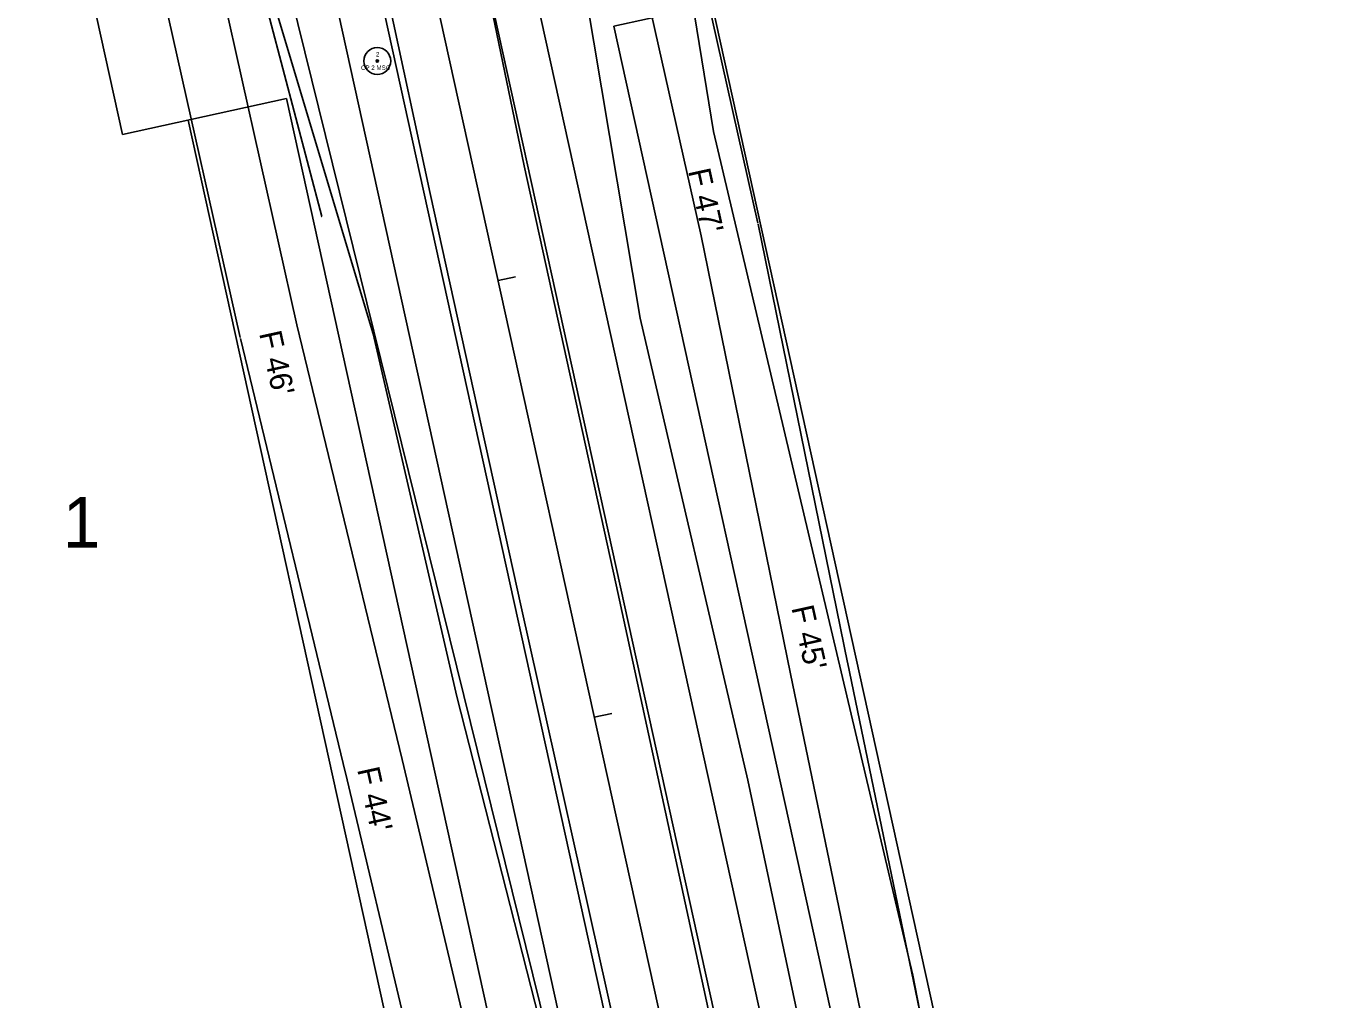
# Model space of a CAD drawing. Extents: x 2519952 to 2531965, y 848341 to 887632.
# Drawn here: x 2524206.7 to 2524500.7, y 856689.7 to 856907.4 of the extents above; entities that cross this region are included whole.
import ezdxf

# ---------------------------------------------------------------- set-up
doc = ezdxf.new("R2010")
doc.units = 0
for name, color, linetype in [('RD_EV_JW', 7, 'Continuous'), ('RD_EX_DV_Prop', 7, 'Continuous'), ('RD_EX_DV_TX_Prop', 7, 'Continuous'), ('RD_EX_H2O', 7, 'Continuous'), ('RD_EX_Road', 7, 'Continuous'), ('RD_EX_RW', 7, 'Continuous'), ('RD_EX_VEG', 7, 'Continuous'), ('RD_HC_Cl', 7, 'Continuous'), ('RD_HC_Data', 7, 'Continuous'), ('RD_HC_Data_Tic', 7, 'Continuous'), ('RD_HC_txCode', 7, 'Continuous'), ('RD_PD_CstnLmt', 7, 'Continuous'), ('RD_PD_DR_ErosCtrl', 7, 'Continuous'), ('RD_PD_Final_TrvlWay', 7, 'Continuous'), ('RD_PD_GR', 7, 'Continuous'), ('RD_PD_RW', 7, 'Continuous'), ('RD_PD_TX_CstnLmt', 7, 'Continuous'), ('RD_SMD_Locator', 7, 'Continuous')]:
    doc.layers.add(name, color=color, linetype=linetype)

msp = doc.modelspace()

# ---------------------------------------------------------------- linework, layer by layer
at = {"layer": 'RD_EV_JW'}
for points in [[(2524424.95, 856473.85), (2524390.5, 856633.35), (2524368.09, 856738.8), (2524344.01, 856842.14), (2524328.51, 856934.61), (2524317.15, 857018.9), (2524297.91, 857028.24)], [(2524307.83, 856393.41), (2524347.51, 856441.44), (2524366.03, 856458.61), (2524362.85, 856506.49), (2524327.82, 856660.19), (2524303.01, 856757.56), (2524284.34, 856838.66), (2524260.99, 856916.53), (2524250.82, 856955.25), (2524240.58, 856992.67)]]:
    msp.add_lwpolyline(points, dxfattribs=at)
at = {"layer": 'RD_EX_DV_Prop'}
for p, q in [((2524163.74, 857176.23), (2524228.26, 856883.25)), ((2524338.13, 856907.45), (2524445.65, 856419.14)), ((2524228.26, 856883.25), (2524264.88, 856891.32)), ((2524264.88, 856891.32), (2524372.41, 856403.02)), ((2524264.88, 856891.32), (2524372.41, 856403.02))]:
    msp.add_line(p, q, dxfattribs=at)
at = {"layer": 'RD_EX_H2O'}
msp.add_lwpolyline([(2524272.81, 856864.89), (2524243.76, 856975.33), (2524236.35, 856986.49), (2524250.55, 857018.32), (2524297.65, 857029.48), (2524307.91, 857029.77)], dxfattribs=at)
at = {"layer": 'RD_EX_Road'}
for p, q in [((2524318.05, 856876.23), (2524297.66, 856974.69)), ((2524297.08, 856870.07), (2524275.55, 856969.68)), ((2524338.64, 856782.48), (2524318.05, 856876.23)), ((2524317.42, 856777.55), (2524297.08, 856870.07)), ((2524359.59, 856685.95), (2524338.64, 856782.48)), ((2524339.18, 856679.93), (2524317.42, 856777.55))]:
    msp.add_line(p, q, dxfattribs=at)
at = {"layer": 'RD_EX_RW'}
for p, q in [((2524163.74, 857176.23), (2524228.26, 856883.25)), ((2524338.13, 856907.44), (2524374.75, 856915.51)), ((2524338.13, 856907.44), (2524445.65, 856419.14)), ((2524228.26, 856883.25), (2524264.88, 856891.32)), ((2524264.88, 856891.32), (2524372.41, 856403.02))]:
    msp.add_line(p, q, dxfattribs=at)
at = {"layer": 'RD_EX_VEG'}
for points in [[(2524280.31, 856341.99), (2524372.33, 856422.74), (2524324.66, 856676.58), (2524252.03, 856970.65), (2524249.14, 857000.39)], [(2524478.83, 856499.73), (2524446.25, 856482.83), (2524405.01, 856695.22), (2524360.42, 856883.93), (2524342.44, 856994.33)]]:
    msp.add_lwpolyline(points, dxfattribs=at)
at = {"layer": 'RD_HC_Cl'}
msp.add_line((2524121.25, 857717.97), (2524677.84, 855190.33), dxfattribs=at)
at = {"layer": 'RD_HC_Data'}
for radius in [3, 0.282]:
    msp.add_circle((2524285.22, 856899.68), radius, dxfattribs=at)
at = {"layer": 'RD_HC_Data_Tic'}
for p, q in [((2524312.26, 856850.55), (2524316.16, 856851.41)), ((2524333.76, 856752.89), (2524337.67, 856753.75))]:
    msp.add_line(p, q, dxfattribs=at)
at = {"layer": 'RD_PD_CstnLmt'}
for p, q in [((2524335.83, 856958.14), (2524357.69, 856860.55)), ((2524245.41, 856938.23), (2524267.26, 856840.64)), ((2524357.69, 856860.55), (2524377.69, 856762.56)), ((2524267.26, 856840.64), (2524290.79, 856743.43)), ((2524377.69, 856762.56), (2524397.95, 856664.63)), ((2524290.79, 856743.43), (2524313.87, 856646.11))]:
    msp.add_line(p, q, dxfattribs=at)
at = {"layer": 'RD_PD_DR_ErosCtrl'}
for p, q in [((2524348.52, 856960.98), (2524370.37, 856863.39)), ((2524232.72, 856935.39), (2524254.57, 856837.8)), ((2524370.43, 856863.15), (2524390.43, 856765.16)), ((2524254.62, 856837.58), (2524278.15, 856740.37)), ((2524390.42, 856765.2), (2524410.68, 856667.26)), ((2524278.14, 856740.43), (2524301.22, 856643.11))]:
    msp.add_line(p, q, dxfattribs=at)
at = {"layer": 'RD_PD_Final_TrvlWay'}
for p, q in [((2524221.83, 857317.02), (2524496.02, 856071.85)), ((2524198.39, 857311.86), (2524472.58, 856066.69))]:
    msp.add_line(p, q, dxfattribs=at)
at = {"layer": 'RD_PD_GR'}
for p, q in [((2524311.97, 856954.16), (2524470.57, 856233.92)), ((2524376.52, 856456.4), (2524269, 856944.7))]:
    msp.add_line(p, q, dxfattribs=at)
at = {"layer": 'RD_PD_RW'}
for p, q in [((2524360.1, 856912.28), (2524467.63, 856423.98)), ((2524242.91, 856886.48), (2524377.31, 856276.1))]:
    msp.add_line(p, q, dxfattribs=at)
at = {"layer": 'RD_SMD_Locator'}
for centre in [(2524285.22, 856899.68), (2524360.42, 856883.93), (2524318.05, 856876.23), (2524297.08, 856870.07), (2524272.81, 856864.89), (2524344.01, 856842.14), (2524284.34, 856838.66), (2524338.64, 856782.48), (2524317.42, 856777.55), (2524303.01, 856757.56), (2524368.09, 856738.8), (2524405.01, 856695.22)]:
    msp.add_circle(centre, 0.001, dxfattribs=at)

# ---------------------------------------------------------------- texts
at = {"layer": 'RD_EX_DV_TX_Prop'}
msp.add_text('1', height=11.32, dxfattribs=at).set_placement((2524214.86, 856790.85))
at = {"layer": 'RD_HC_txCode'}
for s, p in [('2', (2524284.94, 856900.68)), ('CP 2 MSC', (2524281.59, 856897.68))]:
    msp.add_text(s, height=1, dxfattribs=at).set_placement(p)
at = {"layer": 'RD_PD_CstnLmt'}
for s, p in [("F 46'", (2524258.77, 856838.77)), ("F 44'", (2524280.7, 856741.21))]:
    msp.add_text(s, height=5, rotation=282.4185, dxfattribs=at).set_placement(p)
at = {"layer": 'RD_PD_TX_CstnLmt'}
for s, p in [("F 47'", (2524354.73, 856875.11)), ("F 45'", (2524377.83, 856777.38))]:
    msp.add_text(s, height=5, rotation=282.4185, dxfattribs=at).set_placement(p)

doc.saveas('drawing.dxf')
